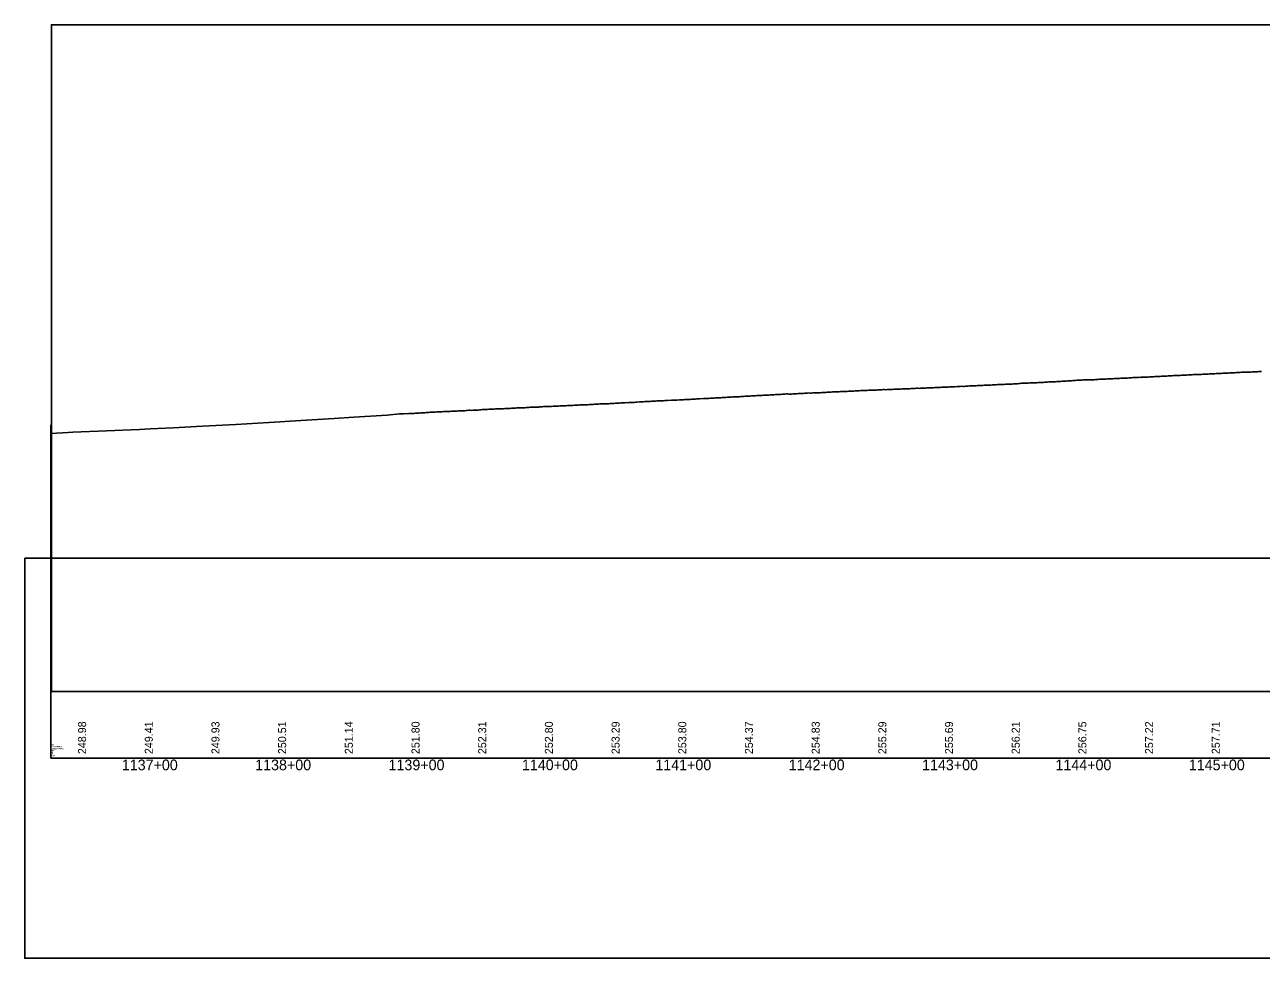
# Model space of a CAD drawing. Extents: x -3627 to 47473, y 2850 to 4350.
# Drawn here: x 980 to 1907, y 2850 to 3550 of the extents above; entities that cross this region are included whole.
import ezdxf

# ---------------------------------------------------------------- set-up
doc = ezdxf.new("R2010")
doc.units = 0
for name, color, linetype in [('RD_DDB_Profile_EX', 7, 'Continuous'), ('RD_DDB_StaTX', 7, 'Continuous'), ('RD_DDB_StripGrade', 7, 'Continuous'), ('RD_GPK_Profile_Cell', 7, 'Continuous'), ('RD_SHT_ShtClip', 7, 'Continuous')]:
    doc.layers.add(name, color=color, linetype=linetype)

msp = doc.modelspace()

# ---------------------------------------------------------------- linework, layer by layer
at = {"layer": 'RD_DDB_Profile_EX'}
for points in [[(1656.792373, 3277.630245), (1657.794903, 3277.63056), (1658.797318, 3277.63182), (1659.793776, 3277.681535), (1660.796309, 3277.77992), (1661.798842, 3277.82931), (1662.787621, 3277.92766), (1663.79004, 3277.97711), (1664.79257, 3277.979305), (1665.794959, 3277.98233), (1666.791563, 3278.030215), (1667.793987, 3278.129665), (1668.79652, 3278.130895), (1669.793122, 3278.22967), (1670.795653, 3278.2309), (1671.798081, 3278.232085), (1672.794543, 3278.281765), (1673.797076, 3278.42954), (1674.807942, 3278.479705), (1675.788261, 3278.430135), (1676.790792, 3278.431325), (1677.809282, 3278.483285), (1679.792224, 3278.63248), (1680.794757, 3278.63439), (1681.807309, 3278.733285), (1682.793879, 3278.881265), (1683.796319, 3278.833165), (1684.792908, 3278.83282), (1685.795317, 3278.93241), (1686.789992, 3278.98335), (1687.786578, 3279.08225), (1688.78902, 3279.18189), (1689.791552, 3279.132995), (1690.788136, 3279.18189), (1691.790666, 3279.282285), (1692.793001, 3279.28337), (1693.789581, 3279.33299), (1694.792113, 3279.43337), (1695.794645, 3279.433745), (1696.797097, 3279.434775), (1697.793673, 3279.483735), (1698.788228, 3279.53409), (1699.79076, 3279.63386), (1700.787256, 3279.68535), (1701.789788, 3279.636335), (1702.79232, 3279.73547), (1703.788891, 3279.73571), (1704.791348, 3279.836065), (1705.793786, 3279.935845), (1706.790353, 3279.984855), (1707.792886, 3279.98643), (1708.795349, 3279.98736), (1709.791914, 3280.13583), (1710.786558, 3280.186815), (1711.789003, 3280.237195), (1712.785564, 3280.287365), (1713.788031, 3280.287185), (1714.790564, 3280.33756), (1715.787123, 3280.387715), (1716.789654, 3280.388595), (1717.792125, 3280.43843), (1718.7886, 3280.53807), (1719.791133, 3280.588935), (1720.793666, 3280.588795), (1721.790161, 3280.68842), (1722.784793, 3280.74029), (1723.787324, 3280.79062), (1724.783803, 3280.84029), (1725.78628, 3280.940615), (1726.788814, 3280.990515), (1727.791347, 3281.140025), (1728.792987, 3281.189645), (1729.795286, 3281.240015), (1730.797635, 3281.290795), (1731.79432, 3281.29042), (1732.796668, 3281.34078), (1733.799016, 3281.391145), (1734.787487, 3281.49098), (1736.057996, 3281.541485), (1737.05464, 3281.5411), (1738.057027, 3281.54183), (1739.053611, 3281.541835), (1740.056042, 3281.642185), (1741.058434, 3281.741845), (1742.055073, 3281.841105), (1743.057504, 3281.842515), (1744.054104, 3281.84252), (1745.056536, 3281.942505), (1746.053136, 3281.99215), (1747.055567, 3282.042835), (1748.057998, 3282.142515), (1749.054598, 3282.24146), (1750.057029, 3282.193155), (1751.053669, 3282.24282), (1752.05606, 3282.293145), (1753.058491, 3282.343785), (1754.055129, 3282.44314), (1755.057522, 3282.493155), (1756.054107, 3282.49346), (1757.056503, 3282.593145), (1758.053139, 3282.693125)], [(1758.053139, 3282.693125), (1759.05557, 3282.74314), (1760.057968, 3282.74378), (1761.054601, 3282.84313), (1762.057033, 3282.893475), (1763.053633, 3282.94312), (1764.056064, 3282.94376), (1765.058496, 3282.99409), (1766.055096, 3283.143155), (1767.057527, 3283.1938), (1768.054127, 3283.243445), (1769.056559, 3283.393225), (1770.053193, 3283.39284), (1771.05559, 3283.393495), (1772.058021, 3283.44439), (1773.054654, 3283.593205), (1774.057009, 3283.64331), (1775.053639, 3283.64291), (1776.056071, 3283.693305), (1777.058475, 3283.743945), (1778.055103, 3283.69383), (1779.057535, 3283.74419), (1780.054134, 3283.843815), (1781.056566, 3283.844175), (1782.053165, 3283.844345), (1783.055597, 3283.894675), (1784.05803, 3283.89548), (1785.054629, 3284.044665), (1786.057061, 3284.144275), (1787.053689, 3284.193895), (1788.056092, 3284.194505), (1789.058525, 3284.24464), (1790.055151, 3284.294495), (1791.057519, 3284.295305), (1792.054143, 3284.39449), (1793.05655, 3284.49462), (1794.053175, 3284.494475), (1795.055608, 3284.544835), (1796.058017, 3284.5454), (1797.054639, 3284.644375), (1798.057072, 3284.744555), (1799.05367, 3284.744815), (1800.056103, 3284.795385), (1801.058536, 3284.84573), (1802.055134, 3284.895165), (1803.057568, 3284.995135), (1804.054165, 3284.99515), (1805.056599, 3284.995705), (1806.053221, 3285.045565), (1807.05563, 3285.09589), (1808.04995, 3285.24629), (1809.046228, 3285.345735), (1810.048689, 3285.346125), (1811.045259, 3285.396065), (1812.047719, 3285.396425), (1813.050179, 3285.446645), (1814.046724, 3285.49626), (1815.049187, 3285.596495), (1816.045773, 3285.64625), (1817.048233, 3285.596765), (1817.689588, 3285.64657), (1818.686291, 3285.696505), (1819.688638, 3285.79685), (1820.685342, 3285.846495), (1821.687672, 3285.84684), (1822.689999, 3285.84731), (1823.686698, 3285.99683), (1824.689032, 3285.99717), (1825.685732, 3285.996675), (1826.688081, 3286.047035), (1827.690429, 3286.14728), (1828.687114, 3286.196895), (1829.681201, 3286.247875), (1830.683535, 3286.248395), (1831.680221, 3286.348045), (1832.682569, 3286.39846), (1833.679264, 3286.398125), (1834.681611, 3286.498305), (1835.683952, 3286.448895), (1836.680645, 3286.54844), (1837.682992, 3286.64865), (1838.678189, 3286.698205), (1839.682016, 3286.79864), (1840.684365, 3286.849), (1841.681056, 3286.94851), (1842.683399, 3286.949075), (1843.68009, 3286.9488), (1844.682438, 3287.04902), (1845.684785, 3287.04939), (1846.681464, 3287.099055), (1847.683814, 3287.199355), (1848.686165, 3287.29968), (1849.682851, 3287.349315), (1850.685198, 3287.3497), (1851.681885, 3287.34936), (1852.684234, 3287.399675), (1853.731756, 3287.50453), (1854.682961, 3287.599615), (1855.700935, 3287.60077), (1856.6823, 3287.64964), (1857.699718, 3287.65075)], [(1857.699718, 3287.65075), (1858.687372, 3287.69961), (1859.729703, 3287.752295), (1860.686396, 3287.79961), (1861.711769, 3287.80146), (1862.67777, 3287.849035), (1863.680503, 3287.8986), (1864.676792, 3287.899045), (1865.679525, 3287.99861), (1866.675813, 3287.99902), (1867.678546, 3288.098625), (1868.68127, 3288.14823), (1869.677561, 3288.24869), (1870.680292, 3288.248385), (1871.683025, 3288.29794), (1872.679325, 3288.348255), (1873.682047, 3288.397865), (1874.678347, 3288.4982), (1875.681069, 3288.497875), (1876.6838, 3288.497585), (1877.680091, 3288.547975), (1878.682822, 3288.697395), (1879.679113, 3288.747735), (1880.681844, 3288.747305), (1881.684561, 3288.79677), (1882.680866, 3288.84742), (1883.683583, 3288.897125), (1884.679903, 3288.89763), (1885.682622, 3288.997025), (1886.685354, 3289.04649), (1887.681644, 3289.09704), (1888.684359, 3289.196375), (1889.680666, 3289.2966), (1890.683381, 3289.34613), (1891.685432, 3289.345805), (1892.684377, 3289.446525), (1893.684452, 3289.495955), (1894.687088, 3289.49584), (1895.686363, 3289.4964), (1896.678384, 3289.595), (1897.67475, 3289.59544), (1898.585566, 3289.59552), (1899.581922, 3289.59594), (1900.576894, 3289.64487), (1901.579583, 3289.694465), (1902.575917, 3289.69508), (1903.578606, 3289.794475), (1904.581296, 3289.84407), (1905.57763, 3289.944065), (1906.580319, 3289.943855), (1907.583008, 3289.8944)], [(1449.167542, 3267.58897), (1450.163778, 3267.738225), (1451.166563, 3267.738575), (1452.162849, 3267.73941), (1453.165583, 3267.788185), (1454.161869, 3267.88864), (1455.164656, 3267.939005), (1456.16089, 3267.989045), (1457.163677, 3267.989015), (1458.159961, 3268.03944), (1459.162635, 3268.039025), (1460.16542, 3268.138185), (1461.161709, 3268.238215), (1462.172898, 3268.189035), (1465.159749, 3268.389865), (1466.162536, 3268.43948), (1467.158823, 3268.53906), (1468.161556, 3268.53823), (1469.171971, 3268.588665), (1471.162248, 3268.736935), (1472.158522, 3268.737835), (1473.169995, 3268.73957), (1474.157608, 3268.839115), (1475.160357, 3268.93784), (1476.156629, 3268.98787), (1477.159322, 3268.988295), (1478.162069, 3269.08653), (1479.158344, 3269.087875), (1480.161091, 3269.186995), (1481.157431, 3269.3366), (1482.16774, 3269.188585), (1483.164014, 3269.23861), (1484.166706, 3269.436915), (1485.163035, 3269.48781), (1486.174186, 3269.53735), (1489.167438, 3269.637785), (1490.163835, 3269.68823), (1491.175266, 3269.738235), (1492.303806, 3269.78808), (1493.306454, 3269.837655), (1494.3113, 3269.938095), (1496.309438, 3269.939215), (1497.298116, 3270.038875), (1498.316522, 3270.18803), (1499.304892, 3270.238125), (1500.301211, 3270.28825), (1501.303915, 3270.33814), (1502.30788, 3270.340095), (1503.304201, 3270.440555), (1504.306903, 3270.39045), (1505.303224, 3270.44122), (1506.305926, 3270.58978), (1507.302297, 3270.689615), (1508.306271, 3270.74121), (1509.308972, 3270.74073), (1510.305294, 3270.842075), (1511.30165, 3270.89225), (1512.304317, 3270.891805), (1513.300672, 3270.942), (1514.311002, 3271.041775), (1515.307326, 3271.04277), (1516.306532, 3271.093475), (1517.309397, 3271.19303), (1518.305549, 3271.243715), (1519.301668, 3271.29395), (1520.304535, 3271.44306), (1521.308041, 3271.44433), (1522.310909, 3271.44385), (1523.307085, 3271.494895), (1524.303204, 3271.59534), (1525.306077, 3271.69473), (1526.302221, 3271.84469), (1527.305705, 3271.846255), (1528.305788, 3271.845795), (1529.307214, 3271.946025), (1530.307619, 3271.94553), (1531.303757, 3271.996165), (1532.299877, 3272.09666), (1533.310129, 3272.04706), (1534.306264, 3272.147455), (1535.302386, 3272.148015), (1536.305281, 3272.14755), (1537.301413, 3272.1981), (1538.297532, 3272.29851), (1539.30043, 3272.44785), (1540.303929, 3272.549185), (1542.302945, 3272.599225), (1543.299067, 3272.649755), (1544.301966, 3272.64922), (1545.467547, 3272.666885), (1546.302783, 3272.74923), (1547.305139, 3272.849595), (1548.301816, 3273.099145), (1549.304173, 3272.949565), (1550.30085, 3272.99917), (1551.297527, 3273.14869), (1552.308136, 3273.148565), (1553.30481, 3273.09827), (1554.301496, 3273.098005), (1555.303844, 3273.048495), (1556.300545, 3273.14809)], [(1556.300545, 3273.14809), (1557.30289, 3273.248405), (1558.299567, 3273.24827), (1559.304501, 3273.3471), (1560.306844, 3273.397555), (1561.303534, 3273.49709), (1562.30021, 3273.44706), (1563.302568, 3273.4475), (1564.299244, 3273.49705), (1565.306524, 3273.6962), (1566.306539, 3273.794915), (1567.300032, 3273.794855), (1568.302672, 3273.895445), (1569.299088, 3273.845435), (1570.295504, 3273.845275), (1571.30593, 3273.944835), (1572.302344, 3274.04446), (1573.304956, 3274.044825), (1573.905136, 3274.09433), (1574.901682, 3274.09448), (1575.904166, 3274.045305), (1576.900712, 3274.09473), (1577.897258, 3274.193845), (1578.907751, 3274.29334), (1579.904344, 3274.29327), (1580.90089, 3274.342585), (1581.903374, 3274.393255), (1582.89992, 3274.4429), (1583.896466, 3274.49254), (1584.90695, 3274.592675), (1585.903552, 3274.741595), (1586.906036, 3274.74231), (1587.902582, 3274.742315), (1588.899128, 3274.791975), (1589.901611, 3274.84194), (1590.906148, 3274.841425), (1591.90276, 3274.89108), (1592.905244, 3274.94141), (1593.90179, 3274.99107), (1594.907189, 3274.990285), (1596.905422, 3275.090175), (1597.901968, 3275.190315), (1598.904452, 3275.289695), (1599.900998, 3275.19079), (1600.903481, 3275.24109), (1601.900027, 3275.34078), (1602.90463, 3275.43945), (1603.907114, 3275.39079), (1604.90366, 3275.391025), (1605.900206, 3275.58857), (1606.902689, 3275.688375), (1607.899235, 3275.73856), (1608.903838, 3275.688265), (1609.906322, 3275.73744), (1610.902868, 3275.83649), (1611.899414, 3275.83672), (1612.901897, 3275.887655), (1613.906399, 3276.03552), (1614.908984, 3276.085265), (1615.90553, 3275.98676), (1616.902076, 3275.98771), (1617.917137, 3276.03927), (1618.901105, 3276.08835), (1619.905597, 3276.18622), (1620.908192, 3276.235855), (1621.904738, 3276.136895), (1622.901284, 3276.284465), (1623.903767, 3276.383435), (1624.900313, 3276.383745), (1625.904916, 3276.334275), (1626.9074, 3276.38461), (1627.903946, 3276.58202), (1628.906429, 3276.53313), (1629.902975, 3276.533505), (1630.899521, 3276.58468), (1631.910062, 3276.68293), (1632.906608, 3276.68257), (1633.903154, 3276.779785), (1634.905637, 3276.78097), (1635.902183, 3276.7822), (1636.898729, 3276.832665), (1637.90927, 3276.930785), (1638.905816, 3276.882115), (1639.902362, 3276.883505), (1640.904845, 3276.933805), (1641.901391, 3277.03089), (1642.903875, 3277.08124), (1643.908478, 3277.082105), (1644.905024, 3277.131775), (1645.907507, 3277.1312), (1646.904053, 3277.229945), (1647.900599, 3277.279585), (1648.89841, 3277.37811), (1649.902763, 3277.378075), (1650.899224, 3277.32964), (1651.90179, 3277.380925), (1652.898216, 3277.528685), (1653.894798, 3277.479325), (1654.897243, 3277.479645), (1655.795758, 3277.58056), (1656.792373, 3277.630245)], [(1347.414794, 3262.49367), (1348.410898, 3262.544055), (1349.41381, 3262.643685), (1350.409915, 3262.69382), (1351.412827, 3262.64422), (1352.408931, 3262.74408), (1353.411843, 3262.793445), (1354.414717, 3262.84306), (1355.410859, 3262.84398), (1356.413774, 3262.94335), (1357.409914, 3262.99347), (1358.412791, 3263.093085), (1359.40893, 3263.143225), (1360.411807, 3263.19282), (1361.407947, 3263.243495), (1362.410823, 3263.243385), (1363.413735, 3263.29185), (1364.40984, 3263.29257), (1365.412752, 3263.293605), (1366.408856, 3263.49286), (1367.411768, 3263.542165), (1368.407872, 3263.59205), (1369.410784, 3263.64131), (1370.413655, 3263.741455), (1371.409801, 3263.74248), (1372.412671, 3263.74269), (1373.403027, 3263.792785), (1374.411688, 3263.7427), (1375.407833, 3263.84308), (1376.410749, 3263.94241), (1377.404763, 3263.99281), (1378.407562, 3263.99242), (1379.410368, 3263.99204), (1380.406588, 3264.04244), (1381.409388, 3264.191415), (1382.405608, 3264.14215), (1383.408407, 3264.14206), (1384.404628, 3264.29216), (1385.407386, 3264.242395), (1386.403648, 3264.292175), (1387.406453, 3264.49083), (1388.409253, 3264.54071), (1389.405473, 3264.541475), (1390.408273, 3264.59139), (1391.404493, 3264.59212), (1392.407249, 3264.641735), (1393.403513, 3264.741815), (1394.406269, 3264.74142), (1395.409067, 3264.83998), (1396.405339, 3264.940445), (1397.408093, 3264.94035), (1398.404358, 3264.94112), (1399.407113, 3264.99105), (1400.403378, 3265.090805), (1401.406133, 3265.09072), (1402.402398, 3265.0918), (1403.405153, 3265.19073), (1404.407958, 3265.240325), (1405.404224, 3265.290405), (1406.406978, 3265.33962), (1407.403244, 3265.44076), (1408.405998, 3265.44035), (1409.402219, 3265.49044), (1410.405017, 3265.590005), (1411.400349, 3265.639205), (1412.404091, 3265.64038), (1413.406843, 3265.68997), (1414.170196, 3265.74122), (1415.173068, 3265.790465), (1416.169214, 3265.74157), (1417.172085, 3265.841535), (1418.168232, 3265.841585), (1419.171103, 3265.94049), (1420.173979, 3265.99082), (1421.170125, 3266.040865), (1422.172997, 3266.090465), (1423.169143, 3266.14123), (1425.166214, 3266.34089), (1426.169, 3266.29122), (1427.165234, 3266.44055), (1428.16802, 3266.53977), (1429.1643, 3266.490905), (1430.16704, 3266.540875), (1431.169768, 3266.689725), (1432.166053, 3266.49197), (1433.176415, 3266.641635), (1434.165073, 3266.741255), (1435.167809, 3266.79089), (1436.164093, 3266.8409), (1437.166879, 3266.840515), (1438.163114, 3266.94055), (1439.173501, 3266.9909), (1441.164919, 3267.18978), (1442.167705, 3267.238575), (1443.163989, 3267.23903), (1444.166725, 3267.288985), (1445.162952, 3267.38942), (1446.165737, 3267.439375), (1447.161972, 3267.48981), (1448.164757, 3267.538995), (1449.167542, 3267.58897)], [(1000, 3243.509345), (1012.80122, 3244.304865), (1016.519117, 3244.46293), (1041.5312, 3245.527655), (1066.489594, 3246.587495), (1074.428313, 3246.924905), (1091.501632, 3247.652055), (1113.682402, 3248.89453), (1138.677894, 3250.29824), (1163.392244, 3251.68514), (1163.719948, 3251.706025), (1187.456999, 3253.18889), (1212.418721, 3254.75026), (1227.009413, 3255.689605), (1252.004058, 3257.299275), (1261.415684, 3258.14428), (1262.41096, 3258.145105), (1263.409572, 3258.194535), (1264.400185, 3258.19487), (1266.393263, 3258.393905), (1267.396091, 3258.343775), (1268.392314, 3258.44416), (1269.395106, 3258.54378), (1270.391297, 3258.594165), (1271.394125, 3258.59379), (1272.390348, 3258.594175), (1273.393178, 3258.644315), (1274.396555, 3258.743425), (1275.392712, 3258.79381), (1276.395536, 3258.793985), (1277.391729, 3258.993565), (1278.394554, 3259.042905), (1279.390785, 3259.093325), (1280.393613, 3259.093195), (1281.389769, 3259.19334), (1282.392631, 3259.243475), (1283.388787, 3259.243865), (1284.391612, 3259.39295), (1285.387805, 3259.492855), (1286.390671, 3259.492425), (1287.38686, 3259.44389), (1288.389688, 3259.54352), (1289.393251, 3259.69406), (1290.396111, 3259.643895), (1291.392269, 3259.74407), (1292.395132, 3259.743915), (1293.391321, 3259.744315), (1294.39415, 3259.893925), (1295.39701, 3259.893795), (1296.393168, 3259.894425), (1297.395993, 3259.94381), (1298.392186, 3259.944435), (1299.39505, 3259.994595), (1300.39124, 3260.193725), (1301.394068, 3260.193835), (1302.390225, 3260.244465), (1303.393086, 3260.343335), (1304.389243, 3260.343755), (1305.392069, 3260.39335), (1306.388297, 3260.44377), (1307.391125, 3260.54311), (1308.387315, 3260.5445), (1309.390143, 3260.4944), (1310.386301, 3260.594275), (1311.389161, 3260.69314), (1312.385354, 3260.84334), (1313.388183, 3260.893415), (1314.391043, 3260.94274), (1315.387201, 3260.84368), (1316.397468, 3260.894165), (1317.393628, 3260.99455), (1318.396454, 3261.04418), (1319.392679, 3260.99479), (1320.395508, 3261.044675), (1321.392566, 3261.1448), (1322.395453, 3261.24372), (1323.391582, 3261.394135), (1324.394469, 3261.443975), (1325.390598, 3261.49415), (1326.393486, 3261.493505), (1327.389614, 3261.543935), (1328.392502, 3261.69352), (1329.38863, 3261.6944), (1330.391518, 3261.69401), (1331.387646, 3261.744635), (1332.390534, 3261.794025), (1333.386662, 3261.893975), (1334.410974, 3261.94407), (1335.413886, 3261.943885), (1336.40999, 3261.994085), (1337.412937, 3261.994135), (1338.415817, 3261.8945), (1339.411953, 3262.094615), (1340.414833, 3262.19376), (1341.410969, 3262.19486), (1342.413849, 3262.244025), (1343.409985, 3262.29417), (1344.412866, 3262.294285), (1345.409002, 3262.44488), (1346.411882, 3262.44454), (1347.414794, 3262.49367)]]:
    msp.add_lwpolyline(points, dxfattribs=at)
at = {"layer": 'RD_GPK_Profile_Cell'}
for q in [(1000, 3250), (46705.077602, 3000), (1000, 3000)]:
    msp.add_line((1000, 3000), q, dxfattribs=at)
at = {"layer": 'RD_SHT_ShtClip'}
for points in [[(2500.165, 3050), (2500.165, 3550), (2500.165, 3550), (1000.33, 3550), (1000.33, 3050)], [(980.33, 3150), (2520, 3150), (2520, 2850), (980.33, 2850)]]:
    msp.add_lwpolyline(points, close=True, dxfattribs=at)

# ---------------------------------------------------------------- texts
at = {"layer": 'RD_DDB_StaTX'}
for s, p in [('1137+00', (1053.125471, 2991)), ('1138+00', (1153.125471, 2991)), ('1139+00', (1253.125471, 2991)), ('1140+00', (1353.125471, 2991)), ('1141+00', (1453.125471, 2991)), ('1142+00', (1553.125471, 2991)), ('1143+00', (1653.125471, 2991)), ('1144+00', (1753.125471, 2991)), ('1145+00', (1853.125471, 2991))]:
    msp.add_text(s, height=8, dxfattribs=at).set_placement(p)
at = {"layer": 'RD_DDB_StripGrade'}
for s, p in [('248.98', (1026.33, 3003.073688)), ('249.41', (1076.33, 3003.073688)), ('249.93', (1126.33, 3003.073688)), ('250.51', (1176.33, 3003.073688)), ('251.14', (1226.33, 3003.073688)), ('251.80', (1276.33, 3003.073688)), ('252.31', (1326.33, 3003.073688)), ('252.80', (1376.33, 3003.073688)), ('253.29', (1426.33, 3003.073688)), ('253.80', (1476.33, 3003.073688)), ('254.37', (1526.33, 3003.073688)), ('254.83', (1576.33, 3003.073688)), ('255.29', (1626.33, 3003.073688)), ('255.69', (1676.33, 3003.073688)), ('256.21', (1726.33, 3003.073688)), ('256.75', (1776.33, 3003.073688)), ('257.22', (1826.33, 3003.073688)), ('257.71', (1876.33, 3003.073688))]:
    msp.add_text(s, height=6, rotation=90, dxfattribs=at).set_placement(p)
at = {"layer": 'RD_GPK_Profile_Cell'}
for s, p in [('002', (1000, 3009.428467)), ('50', (1000, 3004.040772)), ('200', (1000, 3005.387695)), ('113622.670000', (1000, 3006.734619)), ('I77SBLRELO', (1000, 3008.081543)), ('GAP', (1000, 3001.346924)), ('10', (1000, 3002.693848))]:
    msp.add_text(s, height=1, dxfattribs=at).set_placement(p)

doc.saveas('drawing.dxf')
